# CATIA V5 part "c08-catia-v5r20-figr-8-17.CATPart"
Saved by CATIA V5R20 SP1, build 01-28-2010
Part number: Part1
Bounding box of the stored display mesh (mm): x -55.501 to 55.501, y -84.223 to 84.223, z 0 to 81
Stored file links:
  D:\v5_r20\psrt_files_downloaded\c08-catia-v5r20-prt\c08-catia-v5r20-figr-8-17.CATPart
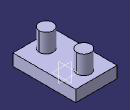
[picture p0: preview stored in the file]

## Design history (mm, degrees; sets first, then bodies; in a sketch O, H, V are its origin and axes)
Body1 (main body)
  Sketch1 on xy-plane, origin (0, 0, 0), H (1, 0, 0), V (0, 1, 0)
    line L1 (-55.501, 84.2232) -> (55.501, 84.2232)
    line L2 (55.501, 84.2232) -> (55.501, -84.2232)
    line L3 (55.501, -84.2232) -> (-55.501, -84.2232)
    line L4 (-55.501, -84.2232) -> (-55.501, 84.2232)
    axis line L5 (55.501, -84.2232) -> (-55.501, 84.2232)
    horizontal: L1 H, L3 H
    vertical: L2 V, L4 V
    midpoint: O L5
  Pad1: profile Sketch1, direction (0, 0, 1), length 31
  Sketch2 on face of Pad1, origin (0, 0, 31), H (1, 0, 0), V (0, 1, 0)
    circle A1 centre (0, -50.4568) radius 18.9426
    point P1 (0, -50.4568)
    coincidence: P1 V
  Pad2: profile Sketch2, direction (0, 0, 1), length 50
  Mirror1: of Pad2, Sketch2, about zx-plane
